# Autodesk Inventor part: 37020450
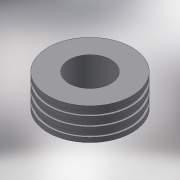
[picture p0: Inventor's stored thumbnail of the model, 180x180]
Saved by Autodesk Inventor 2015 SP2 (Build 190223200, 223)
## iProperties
Created: 2017-08
Part Number: 37020450
Material: Generic
Description: PLASSON MAN HOLE ADAPTOR 450
Document SubType Name: Modeling
Designer: Кирилл
Density: 1 g/cm^3
Appearance: Default
Author: Кирилл
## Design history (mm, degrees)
derived "37020-477207.ipt"
feature "Solid1::37020-477207.ipt"
tag "TaggingFeature1"
body "Solid1"
other parameters: "d0" = 135, "d1" = 592, "d2" = 562.4, "d3" = 397, "L_" = 135, "d_1" = 397, "D_" = 592
